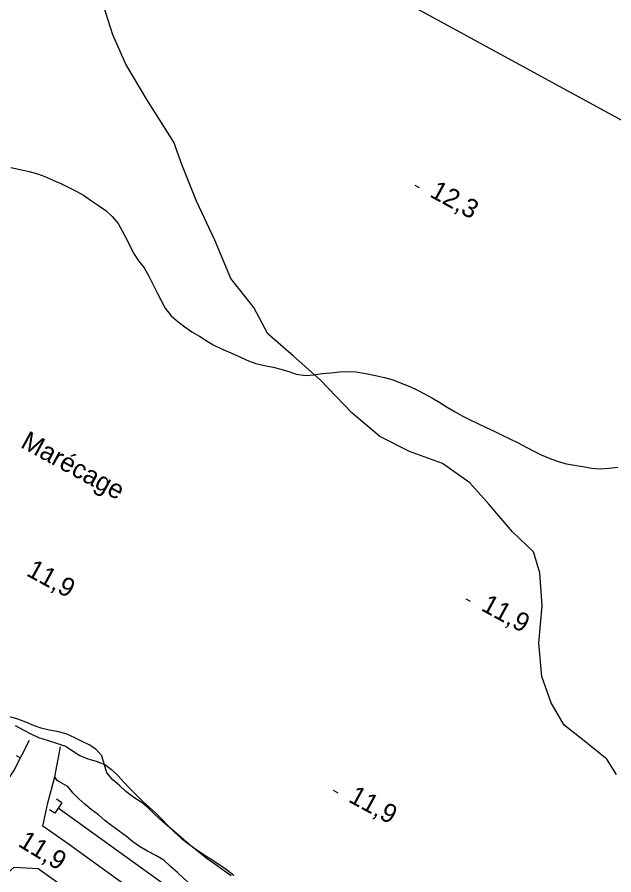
# Model space of a CAD drawing. Extents: x 219136 to 222520, y 5421589 to 5424530.
# Drawn here: x 221476.8 to 221571.8, y 5423515.1 to 5423651.7 of the extents above; entities that cross this region are included whole.
import ezdxf

# ---------------------------------------------------------------- set-up
doc = ezdxf.new("R2010")
doc.units = 0
for name, color, linetype in [('Level 19', 7, 'Continuous'), ('Level 2', 7, 'Continuous'), ('Level 22', 7, 'Continuous'), ('Level 26', 7, 'Continuous'), ('Level 3', 7, 'Continuous'), ('Level 4', 7, 'Continuous'), ('Level 60', 7, 'Continuous'), ('Level 7', 7, 'Continuous')]:
    doc.layers.add(name, color=color, linetype=linetype)

msp = doc.modelspace()

# ---------------------------------------------------------------- linework, layer by layer
at = {"layer": 'Level 19'}
for points in [[(221478.73, 5423536.53), (221476.35, 5423531.85), (221474, 5423528.37), (221470.98, 5423529.32), (221463.67, 5423533.91), (221454.54, 5423539.83), (221446.73, 5423545.33), (221439.11, 5423551.12), (221428.62, 5423558.59), (221418.65, 5423565.88), (221410.54, 5423571.42), (221402.48, 5423576.51), (221397.48, 5423579.26)], [(221579.16, 5423455.01), (221566.87, 5423463.74), (221556.52, 5423471.55), (221545.14, 5423479.31), (221535.59, 5423485.41), (221526, 5423491.73), (221516.87, 5423498.01), (221508.45, 5423503.64), (221501.22, 5423508.52), (221492.49, 5423514.59), (221485.13, 5423519.91), (221480.89, 5423522.85), (221481.7, 5423526.61), (221482.81, 5423530.75), (221483.73, 5423535.49)], [(221435.67, 5423489.92), (221452.64, 5423497.48), (221461.47, 5423500.51), (221469.55, 5423505.36), (221471.66, 5423509.64), (221473.85, 5423514.15), (221476.32, 5423516.36), (221480.18, 5423516.14), (221486.62, 5423511.54), (221500.99, 5423501.74), (221513.95, 5423493.66), (221526.9, 5423485.19), (221540.31, 5423475.77), (221555.17, 5423465.85), (221570.47, 5423455.09), (221587.08, 5423443.28)]]:
    msp.add_lwpolyline(points, dxfattribs=at)
at = {"layer": 'Level 2'}
for points in [[(221475.84, 5423627.73), (221477.32, 5423627.41), (221478.72, 5423627.1), (221480.07, 5423626.7), (221481.25, 5423626.27), (221482.63, 5423625.68), (221483.78, 5423625.18), (221484.96, 5423624.6), (221486.19, 5423623.97), (221487.37, 5423623.33), (221488.67, 5423622.44), (221489.77, 5423621.68), (221490.91, 5423620.86), (221491.96, 5423619.92), (221492.9, 5423618.79), (221493.55, 5423617.63), (221494.21, 5423616.35), (221494.82, 5423615.16), (221495.46, 5423613.93), (221496.15, 5423612.87), (221497.05, 5423611.77), (221497.78, 5423610.41), (221498.43, 5423609.13), (221499.1, 5423607.79), (221499.73, 5423606.57), (221500.37, 5423605.35), (221501.32, 5423604.14), (221502.46, 5423603.15), (221503.5, 5423602.35), (221504.62, 5423601.58), (221505.85, 5423600.86), (221506.92, 5423600.19), (221508.03, 5423599.52), (221509.34, 5423598.85), (221510.8, 5423598.23), (221512.14, 5423597.63), (221513.37, 5423597.06), (221514.81, 5423596.55), (221516.2, 5423596.19), (221517.54, 5423595.94), (221518.78, 5423595.62), (221520.03, 5423595.24), (221521.24, 5423594.83), (221522.74, 5423594.62), (221524.04, 5423594.72), (221525.38, 5423594.92), (221526.76, 5423595.05), (221528.14, 5423595.18)], [(221528.14, 5423595.18), (221529.43, 5423595.23), (221530.73, 5423595.18), (221532.32, 5423594.96), (221533.82, 5423594.62), (221535.25, 5423594.31), (221536.63, 5423593.91), (221537.94, 5423593.41), (221539.31, 5423592.88), (221540.52, 5423592.3), (221541.65, 5423591.69), (221542.89, 5423591), (221544.07, 5423590.31), (221545.27, 5423589.59), (221546.5, 5423588.83), (221547.64, 5423588.18), (221549, 5423587.53), (221550.14, 5423586.95), (221551.45, 5423586.33), (221552.74, 5423585.75), (221553.9, 5423585.16), (221555.2, 5423584.51), (221556.54, 5423583.91), (221557.92, 5423583.17), (221559.04, 5423582.56), (221560.23, 5423581.97), (221561.49, 5423581.43), (221562.9, 5423580.93), (221564.24, 5423580.58), (221565.5, 5423580.34), (221566.83, 5423580.11), (221568.2, 5423579.84), (221569.62, 5423579.77), (221571.05, 5423579.89), (221572.4, 5423580)], [(221476.52, 5423538.91), (221477.78, 5423538.19), (221479.01, 5423537.57), (221480.2, 5423537), (221481.62, 5423536.54), (221483.1, 5423536.09), (221484.49, 5423535.59), (221485.75, 5423534.83), (221486.81, 5423534.1), (221488.06, 5423533.59), (221489.37, 5423533.2), (221490.75, 5423532.68), (221491.83, 5423531.91), (221492.89, 5423530.91), (221493.79, 5423529.88), (221494.68, 5423528.91), (221495.82, 5423527.79), (221496.76, 5423526.86), (221497.82, 5423525.9), (221498.88, 5423524.95), (221499.82, 5423523.99), (221500.78, 5423523), (221501.85, 5423521.9), (221502.9, 5423520.99), (221504.1, 5423520.04), (221505.25, 5423519.23), (221506.41, 5423518.44), (221507.69, 5423517.6), (221508.89, 5423516.82), (221510.08, 5423516.03), (221511.28, 5423515.08)], [(221477.31, 5423533.74), (221476.69, 5423534.05)], [(221505.56, 5423512.81), (221504.31, 5423513.72), (221503.29, 5423514.62), (221502.32, 5423515.5), (221501.24, 5423516.47), (221500.15, 5423517.44), (221498.9, 5423518.23), (221497.58, 5423518.88), (221496.28, 5423519.63), (221495.24, 5423520.4), (221494.21, 5423521.21), (221493.07, 5423522.06), (221491.86, 5423522.91), (221490.79, 5423523.79), (221489.77, 5423524.66), (221488.61, 5423525.55), (221487.59, 5423526.4), (221486.62, 5423527.24), (221485.74, 5423528.13), (221484.88, 5423529.18), (221484.65, 5423529.32), (221483.43, 5423530), (221483.21, 5423530.17), (221482.81, 5423530.73)]]:
    msp.add_lwpolyline(points, dxfattribs=at)
at = {"layer": 'Level 22'}
msp.add_lwpolyline([(221572.22, 5423531.11), (221570.68, 5423533.56), (221566.8, 5423536.68), (221563.89, 5423538.94), (221561.79, 5423542.49), (221560.32, 5423546.71), (221559.85, 5423552.01), (221560.36, 5423557.95), (221560, 5423563.21), (221558.97, 5423566.57), (221555.66, 5423569.74), (221551.93, 5423574.08), (221548.84, 5423577.55), (221544.5, 5423580.61), (221539.25, 5423582.52), (221534.53, 5423584.88), (221530.11, 5423588.62), (221525.06, 5423593.91), (221520.78, 5423597.67), (221516.73, 5423601.24), (221514.49, 5423605.44), (221510.81, 5423610.08), (221508.28, 5423616.18), (221505.34, 5423622.38), (221503.02, 5423628.2), (221501.73, 5423631.76), (221497.48, 5423638.57), (221494.11, 5423644.17), (221492.03, 5423648.85), (221490.57, 5423653.51)], dxfattribs=at)
at = {"layer": 'Level 26'}
for p, q in [((221483.92, 5423526.6), (221483.09, 5423527.16)), ((221483.92, 5423526.6), (221482.81, 5423524.92)), ((221482.81, 5423524.92), (221481.97, 5423525.47))]:
    msp.add_line(p, q, dxfattribs=at)
at = {"layer": 'Level 3'}
for p, q in [((221540.08, 5423624.92), (221540.79, 5423624.53)), ((221548.23, 5423559.06), (221548.93, 5423558.67)), ((221527.13, 5423528.6), (221527.83, 5423528.2))]:
    msp.add_line(p, q, dxfattribs=at)
at = {"layer": 'Level 4'}
msp.add_lwpolyline([(221483.37, 5423525.77), (221507.59, 5423508.33), (221517.94, 5423501.91), (221527.91, 5423494.32), (221536.1, 5423489.58), (221542.9, 5423484.9), (221550.85, 5423479.03), (221558.04, 5423473.03), (221568.21, 5423465.65), (221577.96, 5423458.87)], dxfattribs=at)
at = {"layer": 'Level 60'}
msp.add_lwpolyline([(219164.83, 5422989.67), (219989.85, 5424500.03), (222033.74, 5423383.57), (221208.72, 5421873.21)], close=True, dxfattribs=at)
at = {"layer": 'Level 7'}
msp.add_lwpolyline([(221510.88, 5423514.99), (221509.58, 5423515.87), (221508.26, 5423516.8), (221506.92, 5423517.79), (221505.66, 5423518.81), (221504.48, 5423519.73), (221503.33, 5423520.72), (221502.09, 5423521.79), (221501.14, 5423522.62), (221499.9, 5423523.66), (221498.68, 5423524.78), (221497.62, 5423525.83), (221496.55, 5423526.67), (221495.38, 5423527.43), (221494.14, 5423528.39), (221493.04, 5423529.38), (221492.04, 5423530.26), (221491.08, 5423531.39), (221490.67, 5423532.8), (221490.27, 5423534.08), (221489.34, 5423535.13), (221488.29, 5423535.81), (221487.15, 5423536.37), (221486.01, 5423536.93), (221484.64, 5423537.57), (221483.19, 5423537.94), (221481.93, 5423538.16), (221480.65, 5423538.49), (221479.4, 5423538.91), (221478.19, 5423539.42), (221476.94, 5423539.89), (221475.65, 5423540.28)], dxfattribs=at)

# ---------------------------------------------------------------- texts
at = {"layer": 'Level 3'}
for s, rotation, p in [('12,3', 331.383, (221542.32, 5423623.17)), ('11,9', 331.383, (221478.12, 5423562.86)), ('11,9', 331.383, (221550.47, 5423557.32)), ('11,9', 331.383, (221529.37, 5423526.85)), ('11,9', 328.5587, (221476.8, 5423519.8))]:
    msp.add_text(s, height=3, rotation=rotation, dxfattribs=at).set_placement(p)
at = {"layer": 'Level 7'}
msp.add_text('Marécage', height=3, rotation=331.383, dxfattribs=at).set_placement((221477.2, 5423583.27))

doc.saveas('drawing.dxf')
